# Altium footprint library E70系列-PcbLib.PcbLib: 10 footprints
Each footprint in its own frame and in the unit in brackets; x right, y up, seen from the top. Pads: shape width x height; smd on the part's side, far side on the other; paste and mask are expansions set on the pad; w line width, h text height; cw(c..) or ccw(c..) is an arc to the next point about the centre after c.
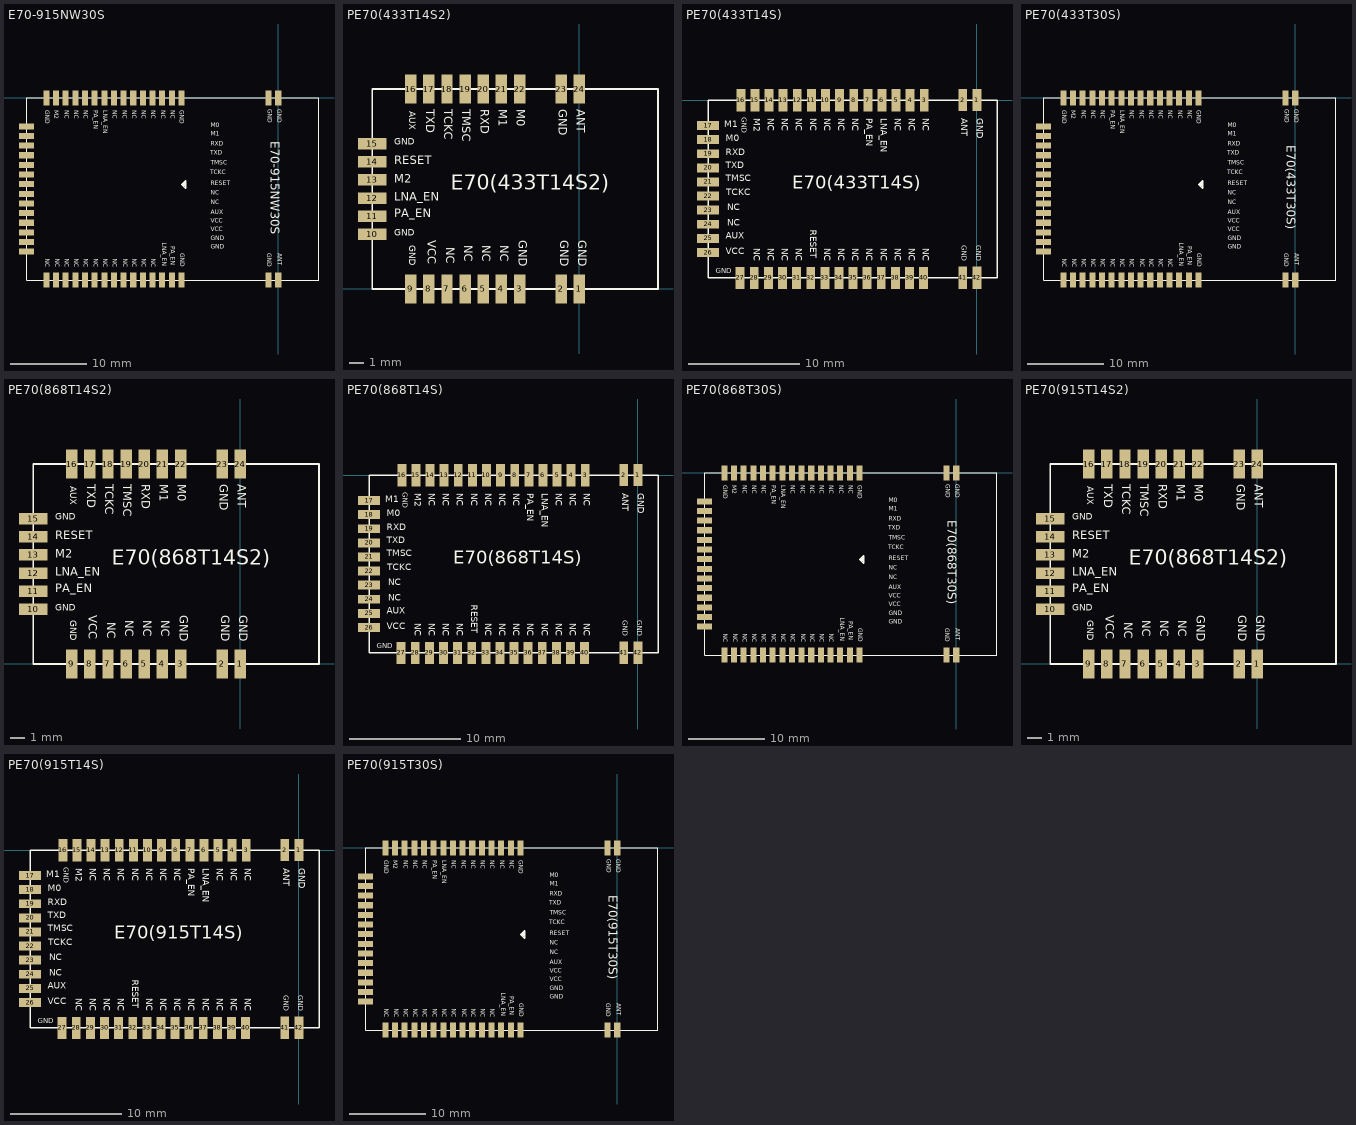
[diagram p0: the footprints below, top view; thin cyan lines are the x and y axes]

## E70-915NW30S [mm]
pads (48):
  rect 0.8x2 smd: 1(0,0) 2(-1.27,0) 3(-12.745,0) 4(-14.015,0) 5(-15.285,0) 6(-16.555,0) 7(-17.825,0) 8(-19.095,0) 9(-20.365,0) 10(-21.635,0) 11(-22.905,0) 12(-24.175,0) 13(-25.445,0) 14(-26.715,0) 15(-27.985,0) 16(-29.255,0) 17(-30.525,0) 32(-30.525,-24) 33(-29.255,-24) 34(-27.985,-24) 35(-26.715,-24) 36(-25.445,-24) 37(-24.175,-24) 38(-22.905,-24) 39(-21.635,-24) 40(-20.365,-24) 41(-19.095,-24) 42(-17.825,-24) 43(-16.555,-24) 44(-15.285,-24) 45(-14.015,-24) 46(-12.745,-24) 47(-1.27,-24) 48(0,-24)
  rect 2x0.8 smd: 18(-33.135,-3.745) 19(-33.135,-5.015) 20(-33.135,-6.285) 21(-33.135,-7.555) 22(-33.135,-8.825) 23(-33.135,-10.095) 24(-33.135,-11.365) 25(-33.135,-12.635) 26(-33.135,-13.905) 27(-33.135,-15.175) 28(-33.135,-16.445) 29(-33.135,-17.715) 30(-33.135,-18.985) 31(-33.135,-20.255)
Top Overlay:
  lines w0.127: -33.135,-24 -33.135,0 5.365,0 5.365,-24 -33.135,-24
  lines w0.2: -12.708,-11.41 -12.202,-11.916 -12.202,-10.908 -12.703,-11.41 ; -12.342,-11.493 -12.342,-11.248 -12.317,-11.222 -12.337,-11.222 -12.475,-11.36 -12.475,-11.406 -12.271,-11.61 -12.271,-11.784
  text "LNA_EN" at -15.494,-19.047 h1
  text "NC" at -8.89,-14.221 h1
  text "RXD" at -8.89,-6.474 h1
  text "NC" at -28.321,-1.648 h1
  text "NC" at -27.051,-1.648 h1
  text "NC" at -25.781,-1.648 h1
  text "NC" at -15.621,-1.648 h1
  text "GND" at -1.651,-20.444 h1
  text "GND" at -8.89,-20.063 h1
  text "GND" at -8.89,-18.92 h1
  text "GND" at -30.861,-1.648 h1
  text "ANT" at -0.254,-20.444 h1
  text "VCC" at -8.89,-17.777 h1
  text "GND" at -1.611,-1.492 h1
  text "GND" at -13.147,-1.612 h1
  text "RESET" at -8.89,-11.681 h1
  text "VCC" at -8.89,-16.634 h1
  text "TCKC" at -8.934,-10.257 h1
  text "TMSC" at -8.904,-8.977 h1
  text "GND" at -0.341,-1.482 h1
  text "M2" at -29.667,-1.61 h1
  text "PA_EN" at -24.511,-1.648 h1
  text "LNA_EN" at -23.241,-1.648 h1
  text "GND" at -13.081,-20.444 h1
  text "NC" at -14.351,-1.648 h1
  text "NC" at -16.891,-1.648 h1
  text "NC" at -18.161,-1.648 h1
  text "NC" at -19.431,-1.648 h1
  text "NC" at -20.701,-1.648 h1
  text "NC" at -21.971,-1.648 h1
  text "M0" at -8.89,-4.061 h1
  text "M1" at -8.89,-5.204 h1
  text "TXD" at -8.928,-7.693 h1
  text "NC" at -8.89,-12.951 h1
  text "AUX" at -8.89,-15.491 h1
  text "NC" at -30.861,-21.206 h1
  text "NC" at -29.591,-21.206 h1
  text "NC" at -28.321,-21.206 h1
  text "NC" at -27.051,-21.206 h1
  text "NC" at -25.781,-21.206 h1
  text "NC" at -24.511,-21.206 h1
  text "NC" at -23.241,-21.206 h1
  text "NC" at -21.971,-21.206 h1
  text "NC" at -20.574,-21.206 h1
  text "NC" at -19.431,-21.206 h1
  text "NC" at -18.161,-21.206 h1
  text "NC" at -16.891,-21.206 h1
  text "PA_EN" at -14.351,-19.555 h1
  text "E70-915NW30S" at -1.397,-5.715 h2

## PE70(433T14S2) [mm] "20mm*14mm*2.57mm-S"
pads (24):
  rect 0.8x2 smd: 1(0,0) 2(-1.27,0) 3(-4.19,0) 4(-5.46,0) 5(-6.73,0) 6(-8,0) 7(-9.27,0) 8(-10.54,0) 9(-11.81,0) 16(-11.81,14) 17(-10.54,14) 18(-9.27,14) 19(-8,14) 20(-6.73,14) 21(-5.46,14) 22(-4.19,14) 23(-1.27,14) 24(0,14)
  rect 2x0.8 smd: 10(-14.5,3.825) 11(-14.5,5.095) 12(-14.5,6.365) 13(-14.5,7.635) 14(-14.5,8.905) 15(-14.5,10.175)
Top Overlay:
  lines w0.127: -14.5,0 5.5,0 5.5,14 -14.5,14 -14.5,0
  text "M0" at -4.594,12.573 h1
  text "M1" at -5.864,12.573 h1
  text "TCKC" at -9.674,12.573 h1
  text "TXD" at -10.944,12.573 h1
  text "AUX" at -12.087,12.446 h0.8
  text "GND" at -12.976,9.906 h0.8
  text "M2" at -12.976,7.239 h1
  text "PA_EN" at -12.976,4.826 h1
  text "GND" at -4.467,3.429 h1
  text "GND" at -0.276,3.429 h1
  text "E70(433T14S2)" at -9.017,6.604 h1.8
  text "GND" at -1.546,3.429 h1
  text "NC" at -5.737,3.048 h1
  text "NC" at -7.007,3.048 h1
  text "NC" at -8.277,3.048 h1
  text "NC" at -9.547,2.921 h1
  text "VCC" at -10.817,3.429 h1
  text "GND" at -12.087,3.048 h0.8
  text "GND" at -12.976,3.556 h0.8
  text "LNA_EN" at -12.976,5.969 h1
  text "RESET" at -12.976,8.509 h1
  text "TMSC" at -8.404,12.573 h1
  text "RXD" at -7.134,12.573 h1
  text "GND" at -1.673,12.573 h1
  text "ANT" at -0.403,12.573 h1

## PE70(433T14S) [mm] "26mm*16mm*2.4mm-S"
pads (42):
  rect 0.8x2 smd: 1(0,0) 2(-1.27,0) 3(-4.735,-0.006) 4(-6.005,-0.006) 5(-7.275,-0.006) 6(-8.545,-0.006) 7(-9.815,-0.006) 8(-11.085,-0.006) 9(-12.355,-0.006) 10(-13.625,-0.006) 11(-14.895,-0.006) 12(-16.165,-0.006) 13(-17.435,-0.006) 14(-18.705,-0.006) 15(-19.975,-0.006) 16(-21.245,-0.006) 27(-21.303,-16.007) 28(-20.033,-16.007) 29(-18.763,-16.007) 30(-17.493,-16.007) 31(-16.223,-16.007) 32(-14.953,-16.007) 33(-13.683,-16.007) 34(-12.413,-16.007) 35(-11.143,-16.007) 36(-9.873,-16.007) 37(-8.603,-16.007) 38(-7.333,-16.007) 39(-6.063,-16.007) 40(-4.793,-16.007) 41(-1.27,-15.996) 42(0,-15.996)
  rect 2x0.8 smd: 17(-24.19,-2.291) 18(-24.19,-3.561) 19(-24.19,-4.831) 20(-24.19,-6.101) 21(-24.19,-7.371) 22(-24.19,-8.641) 23(-24.19,-9.911) 24(-24.19,-11.181) 25(-24.19,-12.451) 26(-24.19,-13.721)
Top Overlay:
  lines w0.127: -24.19,-16.006 1.81,-16.006 1.81,-0.006 -24.19,-0.006 -24.19,-16.006
  text "GND" at -0.254,-13.081 h0.8
  text "GND" at -1.524,-13.081 h0.8
  text "NC" at -5.08,-13.335 h1
  text "NC" at -6.35,-13.335 h1
  text "NC" at -7.62,-13.335 h1
  text "NC" at -8.89,-13.335 h1
  text "NC" at -10.16,-13.335 h1
  text "NC" at -11.43,-13.335 h1
  text "NC" at -12.7,-13.335 h1
  text "NC" at -13.97,-13.335 h1
  text "GND" at -23.495,-15.748 h0.8
  text "NC" at -22.479,-11.557 h1
  text "NC" at -22.479,-10.16 h1
  text "TXD" at -22.606,-6.35 h1
  text "RXD" at -22.606,-5.207 h1
  text "M0" at -22.606,-3.937 h1
  text "GND" at -21.336,-1.524 h0.8
  text "NC" at -19.05,-1.651 h1
  text "NC" at -17.78,-1.651 h1
  text "NC" at -16.51,-1.651 h1
  text "NC" at -15.24,-1.651 h1
  text "NC" at -13.97,-1.651 h1
  text "NC" at -12.7,-1.651 h1
  text "NC" at -11.43,-1.651 h1
  text "NC" at -7.62,-1.651 h1
  text "NC" at -6.35,-1.651 h1
  text "GND" at -0.254,-1.651 h1
  text "ANT" at -1.651,-1.651 h1
  text "NC" at -5.08,-1.651 h1
  text "LNA_EN" at -8.89,-1.651 h1
  text "PA_EN" at -10.16,-1.651 h1
  text "M2" at -20.32,-1.651 h1
  text "M1" at -22.733,-2.667 h1
  text "TCKC" at -22.546,-8.801 h1
  text "AUX" at -22.606,-12.7 h1
  text "VCC" at -22.606,-14.097 h1
  text "RESET" at -15.24,-11.684 h1
  text "TMSC" at -22.594,-7.528 h1
  text "NC" at -20.32,-13.335 h1
  text "NC" at -19.05,-13.335 h1
  text "NC" at -17.78,-13.335 h1
  text "NC" at -16.51,-13.335 h1
  text "E70(433T14S)" at -16.637,-8.382 h2

## PE70(433T30S) [mm] "38.5mm*24mm*3.80mm-S"
pads (48):
  rect 0.8x2 smd: 1(0,0) 2(-1.27,0) 3(-12.745,0) 4(-14.015,0) 5(-15.285,0) 6(-16.555,0) 7(-17.825,0) 8(-19.095,0) 9(-20.365,0) 10(-21.635,0) 11(-22.905,0) 12(-24.175,0) 13(-25.445,0) 14(-26.715,0) 15(-27.985,0) 16(-29.255,0) 17(-30.525,0) 32(-30.525,-24) 33(-29.255,-24) 34(-27.985,-24) 35(-26.715,-24) 36(-25.445,-24) 37(-24.175,-24) 38(-22.905,-24) 39(-21.635,-24) 40(-20.365,-24) 41(-19.095,-24) 42(-17.825,-24) 43(-16.555,-24) 44(-15.285,-24) 45(-14.015,-24) 46(-12.745,-24) 47(-1.27,-24) 48(0,-24)
  rect 2x0.8 smd: 18(-33.135,-3.745) 19(-33.135,-5.015) 20(-33.135,-6.285) 21(-33.135,-7.555) 22(-33.135,-8.825) 23(-33.135,-10.095) 24(-33.135,-11.365) 25(-33.135,-12.635) 26(-33.135,-13.905) 27(-33.135,-15.175) 28(-33.135,-16.445) 29(-33.135,-17.715) 30(-33.135,-18.985) 31(-33.135,-20.255)
Top Overlay:
  lines w0.127: -33.135,-24 -33.135,0 5.365,0 5.365,-24 -33.135,-24
  lines w0.2: -12.708,-11.41 -12.202,-11.916 -12.202,-10.908 -12.703,-11.41 ; -12.342,-11.493 -12.342,-11.248 -12.317,-11.222 -12.337,-11.222 -12.475,-11.36 -12.475,-11.406 -12.271,-11.61 -12.271,-11.784
  text "LNA_EN" at -15.494,-19.047 h1
  text "NC" at -8.89,-14.221 h1
  text "RXD" at -8.89,-6.474 h1
  text "NC" at -28.321,-1.648 h1
  text "NC" at -27.051,-1.648 h1
  text "NC" at -25.781,-1.648 h1
  text "NC" at -15.621,-1.648 h1
  text "GND" at -1.651,-20.444 h1
  text "GND" at -8.89,-20.063 h1
  text "GND" at -8.89,-18.92 h1
  text "GND" at -30.861,-1.648 h1
  text "ANT" at -0.254,-20.444 h1
  text "VCC" at -8.89,-17.777 h1
  text "GND" at -1.611,-1.492 h1
  text "GND" at -13.147,-1.612 h1
  text "RESET" at -8.89,-11.681 h1
  text "VCC" at -8.89,-16.634 h1
  text "TCKC" at -8.934,-10.257 h1
  text "TMSC" at -8.904,-8.977 h1
  text "GND" at -0.341,-1.482 h1
  text "M2" at -29.667,-1.61 h1
  text "PA_EN" at -24.511,-1.648 h1
  text "LNA_EN" at -23.241,-1.648 h1
  text "GND" at -13.081,-20.444 h1
  text "NC" at -14.351,-1.648 h1
  text "NC" at -16.891,-1.648 h1
  text "NC" at -18.161,-1.648 h1
  text "NC" at -19.431,-1.648 h1
  text "NC" at -20.701,-1.648 h1
  text "NC" at -21.971,-1.648 h1
  text "M0" at -8.89,-4.061 h1
  text "M1" at -8.89,-5.204 h1
  text "TXD" at -8.928,-7.693 h1
  text "NC" at -8.89,-12.951 h1
  text "AUX" at -8.89,-15.491 h1
  text "NC" at -30.861,-21.206 h1
  text "NC" at -29.591,-21.206 h1
  text "NC" at -28.321,-21.206 h1
  text "NC" at -27.051,-21.206 h1
  text "NC" at -25.781,-21.206 h1
  text "NC" at -24.511,-21.206 h1
  text "NC" at -23.241,-21.206 h1
  text "NC" at -21.971,-21.206 h1
  text "NC" at -20.574,-21.206 h1
  text "NC" at -19.431,-21.206 h1
  text "NC" at -18.161,-21.206 h1
  text "NC" at -16.891,-21.206 h1
  text "PA_EN" at -14.351,-19.555 h1
  text "E70(433T30S)" at -1.524,-6.22 h2

## PE70(868T14S2) [mm] "20mm*14mm*2.57mm-S"
pads (24):
  rect 0.8x2 smd: 1(0,0) 2(-1.27,0) 3(-4.19,0) 4(-5.46,0) 5(-6.73,0) 6(-8,0) 7(-9.27,0) 8(-10.54,0) 9(-11.81,0) 16(-11.81,14) 17(-10.54,14) 18(-9.27,14) 19(-8,14) 20(-6.73,14) 21(-5.46,14) 22(-4.19,14) 23(-1.27,14) 24(0,14)
  rect 2x0.8 smd: 10(-14.5,3.825) 11(-14.5,5.095) 12(-14.5,6.365) 13(-14.5,7.635) 14(-14.5,8.905) 15(-14.5,10.175)
Top Overlay:
  lines w0.127: -14.5,0 -14.5,14 5.5,14 5.5,0 -14.5,0
  text "ANT" at -0.403,12.573 h1
  text "GND" at -1.673,12.573 h1
  text "RXD" at -7.134,12.573 h1
  text "TMSC" at -8.404,12.573 h1
  text "RESET" at -12.976,8.509 h1
  text "LNA_EN" at -12.976,5.969 h1
  text "GND" at -12.976,3.556 h0.8
  text "GND" at -12.087,3.048 h0.8
  text "VCC" at -10.817,3.429 h1
  text "NC" at -9.547,2.921 h1
  text "NC" at -8.277,3.048 h1
  text "NC" at -7.007,3.048 h1
  text "NC" at -5.737,3.048 h1
  text "GND" at -1.546,3.429 h1
  text "E70(868T14S2)" at -9.017,6.604 h1.8
  text "GND" at -0.276,3.429 h1
  text "GND" at -4.467,3.429 h1
  text "PA_EN" at -12.976,4.826 h1
  text "M2" at -12.976,7.239 h1
  text "GND" at -12.976,9.906 h0.8
  text "AUX" at -12.087,12.446 h0.8
  text "TXD" at -10.944,12.573 h1
  text "TCKC" at -9.674,12.573 h1
  text "M1" at -5.864,12.573 h1
  text "M0" at -4.594,12.573 h1

## PE70(868T14S) [mm] "26mm*16mm*2.4mm-S"
pads (42):
  rect 0.8x2 smd: 1(0,0) 2(-1.27,0) 3(-4.735,-0.006) 4(-6.005,-0.006) 5(-7.275,-0.006) 6(-8.545,-0.006) 7(-9.815,-0.006) 8(-11.085,-0.006) 9(-12.355,-0.006) 10(-13.625,-0.006) 11(-14.895,-0.006) 12(-16.165,-0.006) 13(-17.435,-0.006) 14(-18.705,-0.006) 15(-19.975,-0.006) 16(-21.245,-0.006) 27(-21.303,-16.007) 28(-20.033,-16.007) 29(-18.763,-16.007) 30(-17.493,-16.007) 31(-16.223,-16.007) 32(-14.953,-16.007) 33(-13.683,-16.007) 34(-12.413,-16.007) 35(-11.143,-16.007) 36(-9.873,-16.007) 37(-8.603,-16.007) 38(-7.333,-16.007) 39(-6.063,-16.007) 40(-4.793,-16.007) 41(-1.27,-15.996) 42(0,-15.996)
  rect 2x0.8 smd: 17(-24.19,-2.291) 18(-24.19,-3.561) 19(-24.19,-4.831) 20(-24.19,-6.101) 21(-24.19,-7.371) 22(-24.19,-8.641) 23(-24.19,-9.911) 24(-24.19,-11.181) 25(-24.19,-12.451) 26(-24.19,-13.721)
Top Overlay:
  lines w0.127: -24.19,-16.006 1.81,-16.006 1.81,-0.006 -24.19,-0.006 -24.19,-16.006
  text "GND" at -0.254,-13.081 h0.8
  text "GND" at -1.524,-13.081 h0.8
  text "NC" at -5.08,-13.335 h1
  text "NC" at -6.35,-13.335 h1
  text "NC" at -7.62,-13.335 h1
  text "NC" at -8.89,-13.335 h1
  text "NC" at -10.16,-13.335 h1
  text "NC" at -11.43,-13.335 h1
  text "NC" at -12.7,-13.335 h1
  text "NC" at -13.97,-13.335 h1
  text "GND" at -23.495,-15.748 h0.8
  text "NC" at -22.479,-11.557 h1
  text "NC" at -22.479,-10.16 h1
  text "TXD" at -22.606,-6.35 h1
  text "RXD" at -22.606,-5.207 h1
  text "M0" at -22.606,-3.937 h1
  text "GND" at -21.336,-1.524 h0.8
  text "NC" at -19.05,-1.651 h1
  text "NC" at -17.78,-1.651 h1
  text "NC" at -16.51,-1.651 h1
  text "NC" at -15.24,-1.651 h1
  text "NC" at -13.97,-1.651 h1
  text "NC" at -12.7,-1.651 h1
  text "NC" at -11.43,-1.651 h1
  text "NC" at -7.62,-1.651 h1
  text "NC" at -6.35,-1.651 h1
  text "GND" at -0.254,-1.651 h1
  text "ANT" at -1.651,-1.651 h1
  text "NC" at -5.08,-1.651 h1
  text "LNA_EN" at -8.89,-1.651 h1
  text "PA_EN" at -10.16,-1.651 h1
  text "M2" at -20.32,-1.651 h1
  text "M1" at -22.733,-2.667 h1
  text "TCKC" at -22.546,-8.801 h1
  text "AUX" at -22.606,-12.7 h1
  text "VCC" at -22.606,-14.097 h1
  text "RESET" at -15.24,-11.684 h1
  text "TMSC" at -22.594,-7.528 h1
  text "NC" at -20.32,-13.335 h1
  text "NC" at -19.05,-13.335 h1
  text "NC" at -17.78,-13.335 h1
  text "NC" at -16.51,-13.335 h1
  text "E70(868T14S)" at -16.637,-8.382 h2

## PE70(868T30S) [mm] "38.5mm*24mm*3.80mm-S"
pads (48):
  rect 0.8x2 smd: 1(0,0) 2(-1.27,0) 3(-12.745,0) 4(-14.015,0) 5(-15.285,0) 6(-16.555,0) 7(-17.825,0) 8(-19.095,0) 9(-20.365,0) 10(-21.635,0) 11(-22.905,0) 12(-24.175,0) 13(-25.445,0) 14(-26.715,0) 15(-27.985,0) 16(-29.255,0) 17(-30.525,0) 32(-30.525,-24) 33(-29.255,-24) 34(-27.985,-24) 35(-26.715,-24) 36(-25.445,-24) 37(-24.175,-24) 38(-22.905,-24) 39(-21.635,-24) 40(-20.365,-24) 41(-19.095,-24) 42(-17.825,-24) 43(-16.555,-24) 44(-15.285,-24) 45(-14.015,-24) 46(-12.745,-24) 47(-1.27,-24) 48(0,-24)
  rect 2x0.8 smd: 18(-33.135,-3.745) 19(-33.135,-5.015) 20(-33.135,-6.285) 21(-33.135,-7.555) 22(-33.135,-8.825) 23(-33.135,-10.095) 24(-33.135,-11.365) 25(-33.135,-12.635) 26(-33.135,-13.905) 27(-33.135,-15.175) 28(-33.135,-16.445) 29(-33.135,-17.715) 30(-33.135,-18.985) 31(-33.135,-20.255)
Top Overlay:
  lines w0.127: -33.135,-24 -33.135,0 5.365,0 5.365,-24 -33.135,-24
  lines w0.2: -12.708,-11.41 -12.202,-11.916 -12.202,-10.908 -12.703,-11.41 ; -12.342,-11.493 -12.342,-11.248 -12.317,-11.222 -12.337,-11.222 -12.475,-11.36 -12.475,-11.406 -12.271,-11.61 -12.271,-11.784
  text "LNA_EN" at -15.494,-19.047 h1
  text "NC" at -8.89,-14.221 h1
  text "RXD" at -8.89,-6.474 h1
  text "NC" at -28.321,-1.648 h1
  text "NC" at -27.051,-1.648 h1
  text "NC" at -25.781,-1.648 h1
  text "NC" at -15.621,-1.648 h1
  text "GND" at -1.651,-20.444 h1
  text "GND" at -8.89,-20.063 h1
  text "GND" at -8.89,-18.92 h1
  text "GND" at -30.861,-1.648 h1
  text "ANT" at -0.254,-20.444 h1
  text "VCC" at -8.89,-17.777 h1
  text "GND" at -1.611,-1.492 h1
  text "GND" at -13.147,-1.612 h1
  text "RESET" at -8.89,-11.681 h1
  text "VCC" at -8.89,-16.634 h1
  text "TCKC" at -8.934,-10.257 h1
  text "TMSC" at -8.904,-8.977 h1
  text "GND" at -0.341,-1.482 h1
  text "M2" at -29.667,-1.61 h1
  text "PA_EN" at -24.511,-1.648 h1
  text "LNA_EN" at -23.241,-1.648 h1
  text "GND" at -13.081,-20.444 h1
  text "NC" at -14.351,-1.648 h1
  text "NC" at -16.891,-1.648 h1
  text "NC" at -18.161,-1.648 h1
  text "NC" at -19.431,-1.648 h1
  text "NC" at -20.701,-1.648 h1
  text "NC" at -21.971,-1.648 h1
  text "M0" at -8.89,-4.061 h1
  text "M1" at -8.89,-5.204 h1
  text "TXD" at -8.928,-7.693 h1
  text "NC" at -8.89,-12.951 h1
  text "AUX" at -8.89,-15.491 h1
  text "NC" at -30.861,-21.206 h1
  text "NC" at -29.591,-21.206 h1
  text "NC" at -28.321,-21.206 h1
  text "NC" at -27.051,-21.206 h1
  text "NC" at -25.781,-21.206 h1
  text "NC" at -24.511,-21.206 h1
  text "NC" at -23.241,-21.206 h1
  text "NC" at -21.971,-21.206 h1
  text "NC" at -20.574,-21.206 h1
  text "NC" at -19.431,-21.206 h1
  text "NC" at -18.161,-21.206 h1
  text "NC" at -16.891,-21.206 h1
  text "PA_EN" at -14.351,-19.555 h1
  text "E70(868T30S)" at -1.524,-6.22 h2

## PE70(915T14S2) [mm] "20mm*14mm*2.57mm-S"
pads (24):
  rect 0.8x2 smd: 1(0,0) 2(-1.27,0) 3(-4.19,0) 4(-5.46,0) 5(-6.73,0) 6(-8,0) 7(-9.27,0) 8(-10.54,0) 9(-11.81,0) 16(-11.81,14) 17(-10.54,14) 18(-9.27,14) 19(-8,14) 20(-6.73,14) 21(-5.46,14) 22(-4.19,14) 23(-1.27,14) 24(0,14)
  rect 2x0.8 smd: 10(-14.5,3.825) 11(-14.5,5.095) 12(-14.5,6.365) 13(-14.5,7.635) 14(-14.5,8.905) 15(-14.5,10.175)
Top Overlay:
  lines w0.127: -14.5,0 -14.5,14 5.5,14 5.5,0 -14.5,0
  text "ANT" at -0.403,12.573 h1
  text "GND" at -1.673,12.573 h1
  text "RXD" at -7.134,12.573 h1
  text "TMSC" at -8.404,12.573 h1
  text "RESET" at -12.976,8.509 h1
  text "LNA_EN" at -12.976,5.969 h1
  text "GND" at -12.976,3.556 h0.8
  text "GND" at -12.087,3.048 h0.8
  text "VCC" at -10.817,3.429 h1
  text "NC" at -9.547,2.921 h1
  text "NC" at -8.277,3.048 h1
  text "NC" at -7.007,3.048 h1
  text "NC" at -5.737,3.048 h1
  text "GND" at -1.546,3.429 h1
  text "E70(868T14S2)" at -9.017,6.604 h1.8
  text "GND" at -0.276,3.429 h1
  text "GND" at -4.467,3.429 h1
  text "PA_EN" at -12.976,4.826 h1
  text "M2" at -12.976,7.239 h1
  text "GND" at -12.976,9.906 h0.8
  text "AUX" at -12.087,12.446 h0.8
  text "TXD" at -10.944,12.573 h1
  text "TCKC" at -9.674,12.573 h1
  text "M1" at -5.864,12.573 h1
  text "M0" at -4.594,12.573 h1

## PE70(915T14S) [mm] "26mm*16mm*2.4mm-S"
pads (42):
  rect 0.8x2 smd: 1(0,0) 2(-1.27,0) 3(-4.735,-0.006) 4(-6.005,-0.006) 5(-7.275,-0.006) 6(-8.545,-0.006) 7(-9.815,-0.006) 8(-11.085,-0.006) 9(-12.355,-0.006) 10(-13.625,-0.006) 11(-14.895,-0.006) 12(-16.165,-0.006) 13(-17.435,-0.006) 14(-18.705,-0.006) 15(-19.975,-0.006) 16(-21.245,-0.006) 27(-21.303,-16.007) 28(-20.033,-16.007) 29(-18.763,-16.007) 30(-17.493,-16.007) 31(-16.223,-16.007) 32(-14.953,-16.007) 33(-13.683,-16.007) 34(-12.413,-16.007) 35(-11.143,-16.007) 36(-9.873,-16.007) 37(-8.603,-16.007) 38(-7.333,-16.007) 39(-6.063,-16.007) 40(-4.793,-16.007) 41(-1.27,-15.996) 42(0,-15.996)
  rect 2x0.8 smd: 17(-24.19,-2.291) 18(-24.19,-3.561) 19(-24.19,-4.831) 20(-24.19,-6.101) 21(-24.19,-7.371) 22(-24.19,-8.641) 23(-24.19,-9.911) 24(-24.19,-11.181) 25(-24.19,-12.451) 26(-24.19,-13.721)
Top Overlay:
  lines w0.127: -24.19,-16.006 1.81,-16.006 1.81,-0.006 -24.19,-0.006 -24.19,-16.006
  text "GND" at -0.254,-13.081 h0.8
  text "GND" at -1.524,-13.081 h0.8
  text "NC" at -5.08,-13.335 h1
  text "NC" at -6.35,-13.335 h1
  text "NC" at -7.62,-13.335 h1
  text "NC" at -8.89,-13.335 h1
  text "NC" at -10.16,-13.335 h1
  text "NC" at -11.43,-13.335 h1
  text "NC" at -12.7,-13.335 h1
  text "NC" at -13.97,-13.335 h1
  text "GND" at -23.495,-15.748 h0.8
  text "NC" at -22.479,-11.557 h1
  text "NC" at -22.479,-10.16 h1
  text "TXD" at -22.606,-6.35 h1
  text "RXD" at -22.606,-5.207 h1
  text "M0" at -22.606,-3.937 h1
  text "GND" at -21.336,-1.524 h0.8
  text "NC" at -19.05,-1.651 h1
  text "NC" at -17.78,-1.651 h1
  text "NC" at -16.51,-1.651 h1
  text "NC" at -15.24,-1.651 h1
  text "NC" at -13.97,-1.651 h1
  text "NC" at -12.7,-1.651 h1
  text "NC" at -11.43,-1.651 h1
  text "NC" at -7.62,-1.651 h1
  text "NC" at -6.35,-1.651 h1
  text "GND" at -0.254,-1.651 h1
  text "ANT" at -1.651,-1.651 h1
  text "NC" at -5.08,-1.651 h1
  text "LNA_EN" at -8.89,-1.651 h1
  text "PA_EN" at -10.16,-1.651 h1
  text "M2" at -20.32,-1.651 h1
  text "M1" at -22.733,-2.667 h1
  text "TCKC" at -22.546,-8.801 h1
  text "AUX" at -22.606,-12.7 h1
  text "VCC" at -22.606,-14.097 h1
  text "RESET" at -15.24,-11.684 h1
  text "TMSC" at -22.594,-7.528 h1
  text "NC" at -20.32,-13.335 h1
  text "NC" at -19.05,-13.335 h1
  text "NC" at -17.78,-13.335 h1
  text "NC" at -16.51,-13.335 h1
  text "E70(915T14S)" at -16.637,-8.382 h2

## PE70(915T30S) [mm] "38.5mm*24mm*3.80mm-S"
pads (48):
  rect 0.8x2 smd: 1(0,0) 2(-1.27,0) 3(-12.745,0) 4(-14.015,0) 5(-15.285,0) 6(-16.555,0) 7(-17.825,0) 8(-19.095,0) 9(-20.365,0) 10(-21.635,0) 11(-22.905,0) 12(-24.175,0) 13(-25.445,0) 14(-26.715,0) 15(-27.985,0) 16(-29.255,0) 17(-30.525,0) 32(-30.525,-24) 33(-29.255,-24) 34(-27.985,-24) 35(-26.715,-24) 36(-25.445,-24) 37(-24.175,-24) 38(-22.905,-24) 39(-21.635,-24) 40(-20.365,-24) 41(-19.095,-24) 42(-17.825,-24) 43(-16.555,-24) 44(-15.285,-24) 45(-14.015,-24) 46(-12.745,-24) 47(-1.27,-24) 48(0,-24)
  rect 2x0.8 smd: 18(-33.135,-3.745) 19(-33.135,-5.015) 20(-33.135,-6.285) 21(-33.135,-7.555) 22(-33.135,-8.825) 23(-33.135,-10.095) 24(-33.135,-11.365) 25(-33.135,-12.635) 26(-33.135,-13.905) 27(-33.135,-15.175) 28(-33.135,-16.445) 29(-33.135,-17.715) 30(-33.135,-18.985) 31(-33.135,-20.255)
Top Overlay:
  lines w0.127: -33.135,-24 -33.135,0 5.365,0 5.365,-24 -33.135,-24
  lines w0.2: -12.708,-11.41 -12.202,-11.916 -12.202,-10.908 -12.703,-11.41 ; -12.342,-11.493 -12.342,-11.248 -12.317,-11.222 -12.337,-11.222 -12.475,-11.36 -12.475,-11.406 -12.271,-11.61 -12.271,-11.784
  text "LNA_EN" at -15.494,-19.047 h1
  text "NC" at -8.89,-14.221 h1
  text "RXD" at -8.89,-6.474 h1
  text "NC" at -28.321,-1.648 h1
  text "NC" at -27.051,-1.648 h1
  text "NC" at -25.781,-1.648 h1
  text "NC" at -15.621,-1.648 h1
  text "GND" at -1.651,-20.444 h1
  text "GND" at -8.89,-20.063 h1
  text "GND" at -8.89,-18.92 h1
  text "GND" at -30.861,-1.648 h1
  text "ANT" at -0.254,-20.444 h1
  text "VCC" at -8.89,-17.777 h1
  text "GND" at -1.611,-1.492 h1
  text "GND" at -13.147,-1.612 h1
  text "RESET" at -8.89,-11.681 h1
  text "VCC" at -8.89,-16.634 h1
  text "TCKC" at -8.934,-10.257 h1
  text "TMSC" at -8.904,-8.977 h1
  text "GND" at -0.341,-1.482 h1
  text "M2" at -29.667,-1.61 h1
  text "PA_EN" at -24.511,-1.648 h1
  text "LNA_EN" at -23.241,-1.648 h1
  text "GND" at -13.081,-20.444 h1
  text "NC" at -14.351,-1.648 h1
  text "NC" at -16.891,-1.648 h1
  text "NC" at -18.161,-1.648 h1
  text "NC" at -19.431,-1.648 h1
  text "NC" at -20.701,-1.648 h1
  text "NC" at -21.971,-1.648 h1
  text "M0" at -8.89,-4.061 h1
  text "M1" at -8.89,-5.204 h1
  text "TXD" at -8.928,-7.693 h1
  text "NC" at -8.89,-12.951 h1
  text "AUX" at -8.89,-15.491 h1
  text "NC" at -30.861,-21.206 h1
  text "NC" at -29.591,-21.206 h1
  text "NC" at -28.321,-21.206 h1
  text "NC" at -27.051,-21.206 h1
  text "NC" at -25.781,-21.206 h1
  text "NC" at -24.511,-21.206 h1
  text "NC" at -23.241,-21.206 h1
  text "NC" at -21.971,-21.206 h1
  text "NC" at -20.574,-21.206 h1
  text "NC" at -19.431,-21.206 h1
  text "NC" at -18.161,-21.206 h1
  text "NC" at -16.891,-21.206 h1
  text "PA_EN" at -14.351,-19.555 h1
  text "E70(915T30S)" at -1.524,-6.22 h2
